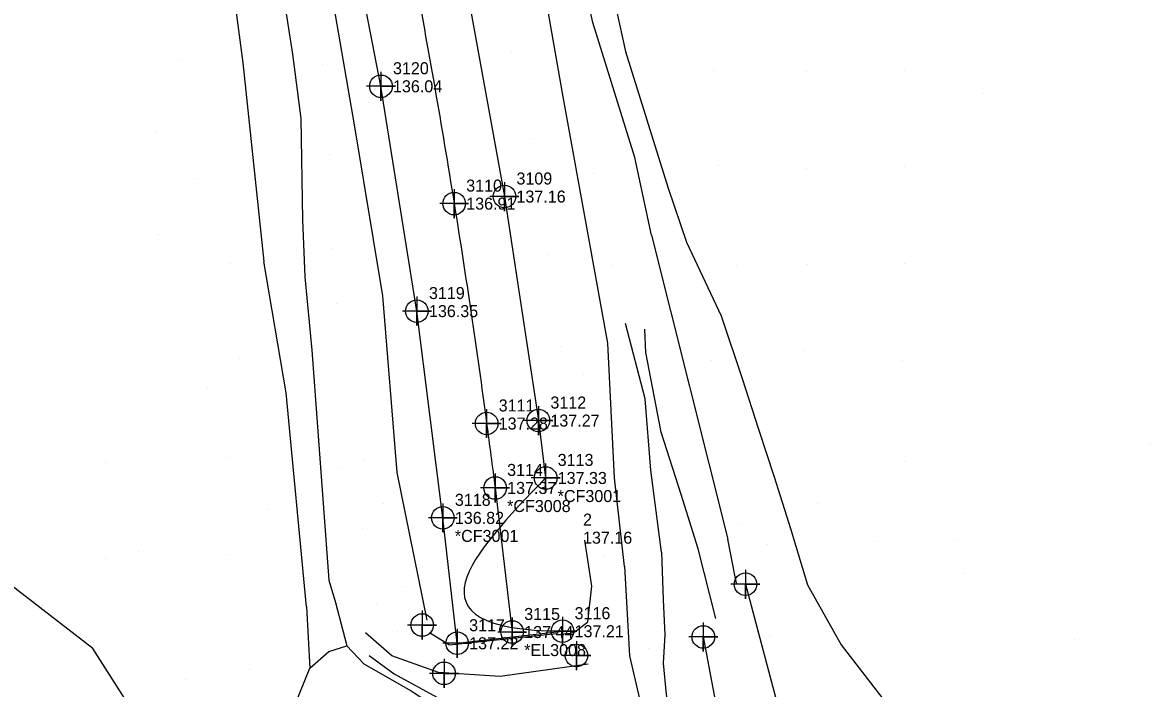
# Model space of a CAD drawing. Extents: x 2312183 to 2312663, y 819676 to 820746.
# Drawn here: x 2312371.9 to 2312606.3, y 820186.5 to 820324.9 of the extents above; entities that cross this region are included whole.
import ezdxf

# ---------------------------------------------------------------- set-up
doc = ezdxf.new("R2010")
doc.units = 0
for name, color, linetype in [('CTL Supplemental Horizontal and Vertical Cogo Elevation', 7, 'Continuous'), ('CTL Supplemental Horizontal and Vertical Cogo Number', 7, 'Continuous'), ('Exist DTM Breakline', 7, 'Continuous'), ('Exist DTM Breakline Cogo Point CELL', 7, 'Continuous'), ('Exist DTM Crownline', 7, 'Continuous'), ('Exist DTM Crownline Cogo Comment', 7, 'Continuous'), ('Exist DTM Crownline Cogo Elevation', 7, 'Continuous'), ('Exist DTM Crownline Cogo Number', 7, 'Continuous'), ('Exist DTM Crownline Cogo Point CELL', 7, 'Continuous'), ('Exist DTM Regular Point CELL', 7, 'Continuous'), ('Exist Roads EOP', 7, 'Continuous'), ('Exist Roads EOP Cogo Comment', 7, 'Continuous'), ('Exist Roads EOP Cogo Elevation', 7, 'Continuous'), ('Exist Roads EOP Cogo Number', 7, 'Continuous'), ('Exist Roads EOP Cogo Point CELL', 7, 'Continuous'), ('PH Exist DTM Breakline', 7, 'Continuous'), ('PH Exist DTM Point', 7, 'Continuous')]:
    doc.layers.add(name, color=color, linetype=linetype)

msp = doc.modelspace()

# ---------------------------------------------------------------- linework, layer by layer
at = {"layer": 'Exist DTM Breakline'}
for points in [[(2312522.0978, 820208.185), (2312528.7148, 820183.411), (2312536.4050000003, 820173.6053), (2312549.6083000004, 820163.9883)], [(2312513.3468, 820197.2374000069), (2312517.1413, 820177.0220999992)]]:
    msp.add_lwpolyline(points, dxfattribs=at)
at = {"layer": 'Exist DTM Breakline Cogo Point CELL'}
for points in [[(2312522.0978, 820211.1849999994), (2312522.0978, 820205.1849999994), (2312522.0978, 820208.1849999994), (2312525.0978, 820208.1849999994), (2312519.0978, 820208.1849999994)], [(2312513.3468, 820200.2374000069), (2312513.3468, 820194.2374000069), (2312513.3468, 820197.2374000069), (2312516.3468, 820197.2374000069), (2312510.3468, 820197.2374000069)]]:
    msp.add_lwpolyline(points, dxfattribs=at)
for centre in [(2312522.0978, 820208.1849999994), (2312513.3468, 820197.2374000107)]:
    msp.add_circle(centre, 2.344041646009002, dxfattribs=at)
at = {"layer": 'Exist DTM Crownline'}
msp.add_line((2312470.0837, 820228.1889), (2312473.6335, 820198.2664), dxfattribs=at)
msp.add_spline([(2312431.0822000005, 820427.0948), (2312442.7462, 820383.7602), (2312453.1289000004, 820335.5615000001), (2312461.5818, 820287.2566), (2312468.3305, 820241.5777), (2312470.0837, 820228.1889)], degree=3, dxfattribs=at)
at = {"layer": 'Exist DTM Crownline Cogo Point CELL'}
for points in [[(2312461.5818, 820290.2565999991), (2312461.5818, 820284.2565999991), (2312461.5818, 820287.2565999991), (2312464.5818, 820287.2565999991), (2312458.5818, 820287.2565999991)], [(2312461.5818, 820290.2565999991), (2312461.5818, 820284.2565999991), (2312461.5818, 820287.2565999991), (2312464.5818, 820287.2565999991), (2312458.5818, 820287.2565999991)], [(2312468.3305, 820244.5776999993), (2312468.3305, 820238.5776999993), (2312468.3305, 820241.5776999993), (2312471.3305, 820241.5776999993), (2312465.3305, 820241.5776999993)], [(2312468.3305, 820244.5776999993), (2312468.3305, 820238.5776999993), (2312468.3305, 820241.5776999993), (2312471.3305, 820241.5776999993), (2312465.3305, 820241.5776999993)], [(2312470.0837, 820231.1889000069), (2312470.0837, 820225.1889000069), (2312470.0837, 820228.1889000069), (2312473.0837, 820228.1889000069), (2312467.0837, 820228.1889000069)], [(2312470.0837, 820231.1889000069), (2312470.0837, 820225.1889000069), (2312470.0837, 820228.1889000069), (2312473.0837, 820228.1889000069), (2312467.0837, 820228.1889000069)], [(2312473.6335, 820201.266400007), (2312473.6335, 820195.266400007), (2312473.6335, 820198.266400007), (2312476.6335, 820198.266400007), (2312470.6335, 820198.266400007)], [(2312473.6335, 820201.266400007), (2312473.6335, 820195.266400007), (2312473.6335, 820198.266400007), (2312476.6335, 820198.266400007), (2312470.6335, 820198.266400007)]]:
    msp.add_lwpolyline(points, dxfattribs=at)
for centre in [(2312461.5818, 820287.2565999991), (2312461.5818, 820287.2565999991), (2312468.3305, 820241.5776999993), (2312468.3305, 820241.5776999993), (2312470.0837, 820228.1889000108), (2312470.0837, 820228.1889000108), (2312473.6335, 820198.2664000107), (2312473.6335, 820198.2664000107)]:
    msp.add_circle(centre, 2.344041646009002, dxfattribs=at)
at = {"layer": 'Exist DTM Regular Point CELL'}
for points in [[(2312454.915, 820202.7199999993), (2312454.915, 820196.7199999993), (2312454.915, 820199.7199999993), (2312457.915, 820199.7199999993), (2312451.915, 820199.7199999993)], [(2312486.9797, 820196.3685999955), (2312486.9797, 820190.3685999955), (2312486.9797, 820193.3685999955), (2312489.9797, 820193.3685999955), (2312483.9797, 820193.3685999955)], [(2312459.4753, 820192.6829000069), (2312459.4753, 820186.6829000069), (2312459.4753, 820189.6829000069), (2312462.4753, 820189.6829000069), (2312456.4753, 820189.6829000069)]]:
    msp.add_lwpolyline(points, dxfattribs=at)
for centre in [(2312454.915, 820199.7199999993), (2312486.9797, 820193.3685999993), (2312459.4753, 820189.6829000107)]:
    msp.add_circle(centre, 2.344041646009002, dxfattribs=at)
at = {"layer": 'Exist Roads EOP'}
msp.add_line((2312462.1894999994, 820195.9283000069), (2312459.2241, 820221.9777), dxfattribs=at)
for points in [[(2312441.0535, 820429.753), (2312452.7654, 820386.6268), (2312463.4794, 820336.0054), (2312472.0187, 820288.7267000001), (2312479.0736, 820242.1885), (2312480.5877, 820230.2653)], [(2312459.2241, 820221.9777), (2312453.8417, 820264.9341), (2312446.3695, 820311.6319000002), (2312437.1934, 820358.8933), (2312425.9943, 820405.6538), (2312419.7593, 820426.9969)], [(2312462.1895, 820195.928300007), (2312484.0977, 820198.4309999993)]]:
    msp.add_lwpolyline(points, dxfattribs=at)
msp.add_spline([(2312480.5877, 820230.2653), (2312484.0977, 820198.431), (2312484.0977, 820198.4309999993)], degree=3, dxfattribs=at)
at = {"layer": 'Exist Roads EOP Cogo Point CELL'}
for points in [[(2312446.3695, 820314.6318999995), (2312446.3695, 820308.6318999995), (2312446.3695, 820311.6318999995), (2312449.3695, 820311.6318999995), (2312443.3695, 820311.6318999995)], [(2312446.3695, 820314.6318999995), (2312446.3695, 820308.6318999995), (2312446.3695, 820311.6318999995), (2312449.3695, 820311.6318999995), (2312443.3695, 820311.6318999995)], [(2312446.3695, 820314.6318999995), (2312446.3695, 820308.6318999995), (2312446.3695, 820311.6318999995), (2312449.3695, 820311.6318999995), (2312443.3695, 820311.6318999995)], [(2312472.0187, 820291.7266999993), (2312472.0187, 820285.7266999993), (2312472.0187, 820288.7266999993), (2312475.0187, 820288.7266999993), (2312469.0187, 820288.7266999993)], [(2312472.0187, 820291.7266999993), (2312472.0187, 820285.7266999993), (2312472.0187, 820288.7266999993), (2312475.0187, 820288.7266999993), (2312469.0187, 820288.7266999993)], [(2312472.0187, 820291.7266999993), (2312472.0187, 820285.7266999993), (2312472.0187, 820288.7266999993), (2312475.0187, 820288.7266999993), (2312469.0187, 820288.7266999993)], [(2312453.8417, 820267.9340999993), (2312453.8417, 820261.9340999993), (2312453.8417, 820264.9340999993), (2312456.8417, 820264.9340999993), (2312450.8417, 820264.9340999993)], [(2312453.8417, 820267.9340999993), (2312453.8417, 820261.9340999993), (2312453.8417, 820264.9340999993), (2312456.8417, 820264.9340999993), (2312450.8417, 820264.9340999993)], [(2312453.8417, 820267.9340999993), (2312453.8417, 820261.9340999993), (2312453.8417, 820264.9340999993), (2312456.8417, 820264.9340999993), (2312450.8417, 820264.9340999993)], [(2312479.0736, 820245.1884999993), (2312479.0736, 820239.1884999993), (2312479.0736, 820242.1884999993), (2312482.0736, 820242.1884999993), (2312476.0736, 820242.1884999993)], [(2312479.0736, 820245.1884999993), (2312479.0736, 820239.1884999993), (2312479.0736, 820242.1884999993), (2312482.0736, 820242.1884999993), (2312476.0736, 820242.1884999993)], [(2312479.0736, 820245.1884999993), (2312479.0736, 820239.1884999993), (2312479.0736, 820242.1884999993), (2312482.0736, 820242.1884999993), (2312476.0736, 820242.1884999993)], [(2312480.5877, 820233.2652999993), (2312480.5877, 820227.2652999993), (2312480.5877, 820230.2652999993), (2312483.5877, 820230.2652999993), (2312477.5877, 820230.2652999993)], [(2312480.5877, 820233.2652999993), (2312480.5877, 820227.2652999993), (2312480.5877, 820230.2652999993), (2312483.5877, 820230.2652999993), (2312477.5877, 820230.2652999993)], [(2312480.5877, 820233.2652999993), (2312480.5877, 820227.2652999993), (2312480.5877, 820230.2652999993), (2312483.5877, 820230.2652999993), (2312477.5877, 820230.2652999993)], [(2312459.2241, 820224.9776999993), (2312459.2241, 820218.9776999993), (2312459.2241, 820221.9776999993), (2312462.2241, 820221.9776999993), (2312456.2241, 820221.9776999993)], [(2312459.2241, 820224.9776999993), (2312459.2241, 820218.9776999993), (2312459.2241, 820221.9776999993), (2312462.2241, 820221.9776999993), (2312456.2241, 820221.9776999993)], [(2312459.2241, 820224.9776999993), (2312459.2241, 820218.9776999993), (2312459.2241, 820221.9776999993), (2312462.2241, 820221.9776999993), (2312456.2241, 820221.9776999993)], [(2312484.0977, 820201.4309999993), (2312484.0977, 820195.4309999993), (2312484.0977, 820198.4309999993), (2312487.0977, 820198.4309999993), (2312481.0977, 820198.4309999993)], [(2312484.0977, 820201.4309999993), (2312484.0977, 820195.4309999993), (2312484.0977, 820198.4309999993), (2312487.0977, 820198.4309999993), (2312481.0977, 820198.4309999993)], [(2312484.0977, 820201.4309999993), (2312484.0977, 820195.4309999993), (2312484.0977, 820198.4309999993), (2312487.0977, 820198.4309999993), (2312481.0977, 820198.4309999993)], [(2312462.1895, 820198.928300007), (2312462.1895, 820192.928300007), (2312462.1895, 820195.928300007), (2312465.1895, 820195.928300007), (2312459.1895, 820195.928300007)], [(2312462.1895, 820198.928300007), (2312462.1895, 820192.928300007), (2312462.1895, 820195.928300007), (2312465.1895, 820195.928300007), (2312459.1895, 820195.928300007)], [(2312462.1895, 820198.928300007), (2312462.1895, 820192.928300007), (2312462.1895, 820195.928300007), (2312465.1895, 820195.928300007), (2312459.1895, 820195.928300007)]]:
    msp.add_lwpolyline(points, dxfattribs=at)
for centre in [(2312446.3695, 820311.6318999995), (2312446.3695, 820311.6318999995), (2312446.3695, 820311.6318999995), (2312472.0187, 820288.7266999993), (2312472.0187, 820288.7266999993), (2312472.0187, 820288.7266999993), (2312453.8417, 820264.9340999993), (2312453.8417, 820264.9340999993), (2312453.8417, 820264.9340999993), (2312479.0736, 820242.1884999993), (2312479.0736, 820242.1884999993), (2312479.0736, 820242.1884999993), (2312480.5877, 820230.2652999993), (2312480.5877, 820230.2652999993), (2312480.5877, 820230.2652999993), (2312459.2241, 820221.9776999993), (2312459.2241, 820221.9776999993), (2312459.2241, 820221.9776999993), (2312484.0977, 820198.4309999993), (2312484.0977, 820198.4309999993), (2312484.0977, 820198.4309999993), (2312462.1895, 820195.9283000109), (2312462.1895, 820195.9283000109), (2312462.1895, 820195.9283000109)]:
    msp.add_circle(centre, 2.344041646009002, dxfattribs=at)
at = {"layer": 'PH Exist DTM Breakline'}
for points in [[(2312496.9827015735, 820211.8866744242), (2312494.8731904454, 820230.3124907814), (2312493.519987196, 820258.2712960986), (2312489.5697944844, 820280.073130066), (2312484.2208748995, 820309.4534036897), (2312481.150772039, 820326.8098322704), (2312475.4411637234, 820352.0844131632), (2312471.9095048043, 820367.9236878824), (2312467.912111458, 820381.4585456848), (2312463.4561038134, 820397.0129259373), (2312457.4207705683, 820416.5983887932), (2312453.9249898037, 820433.7888603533), (2312449.599353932, 820447.3666451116), (2312444.372751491, 820464.2727058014), (2312438.966790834, 820481.2008368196), (2312434.255033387, 820489.9728212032), (2312425.0514561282, 820503.8371172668), (2312418.259878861, 820512.3555225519), (2312411.0550560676, 820524.7736185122), (2312404.5014063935, 820537.3120355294), (2312396.0707229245, 820550.9142930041), (2312386.9718457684, 820563.2584496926), (2312378.040674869, 820577.4175645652), (2312367.5173050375, 820592.3718469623)], [(2312323.1852827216, 820565.0943421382), (2312341.16408717, 820534.9037687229), (2312360.245174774, 820506.1026928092), (2312372.4134060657, 820480.8900151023), (2312378.9962576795, 820463.915286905), (2312383.7723335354, 820454.9488229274), (2312388.746726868, 820444.6210026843), (2312396.2505561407, 820429.0479748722), (2312399.85680621, 820410.3493696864), (2312407.6810818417, 820378.7675660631), (2312412.990038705, 820355.2448037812), (2312416.1657901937, 820328.0193103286), (2312417.670236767, 820316.518029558), (2312422.048230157, 820275.2675484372)], [(2312457.310195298, 820470.8861366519), (2312462.7773111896, 820457.1940474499), (2312468.029919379, 820441.2262342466), (2312476.135823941, 820415.8221279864), (2312481.1635680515, 820399.2820110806), (2312486.56663762, 820374.1366036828), (2312491.175310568, 820346.3471255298), (2312497.1618455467, 820318.8853012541), (2312506.0476551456, 820290.4807863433), (2312509.857743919, 820279.2465673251), (2312517.034249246, 820263.9694193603), (2312521.4019957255, 820250.9366621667), (2312524.806534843, 820240.42459485), (2312528.0448119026, 820230.484835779), (2312531.475516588, 820219.8051016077)], [(2312391.1625844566, 820470.3831024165), (2312395.47620005, 820461.7769371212), (2312400.382861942, 820454.8597855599), (2312403.1375107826, 820447.0263515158), (2312404.5621205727, 820436.917011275), (2312406.087167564, 820429.8943630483), (2312407.398139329, 820424.4934151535), (2312408.6872812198, 820418.1584440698), (2312410.6680697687, 820411.7899121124), (2312412.8573282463, 820405.2837896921), (2312415.74816436, 820396.579647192), (2312418.226217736, 820388.7645800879), (2312419.520083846, 820381.7036929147), (2312419.4184755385, 820374.2083282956), (2312421.1745975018, 820356.993459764), (2312423.458423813, 820344.7491194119), (2312425.7778383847, 820332.5817705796), (2312428.009826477, 820318.2808153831), (2312429.6954572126, 820304.9376266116), (2312430.078320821, 820283.9125766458), (2312430.5516890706, 820272.0198299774), (2312432.00627728, 820256.8034783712), (2312435.527714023, 820209.0178143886), (2312436.9438508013, 820204.4279931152)], [(2312455.9897626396, 820200.7254818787), (2312449.7528222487, 820231.3712196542), (2312446.7479994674, 820268.1101860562), (2312440.8961120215, 820303.6189076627), (2312436.924257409, 820326.4967031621), (2312429.9949859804, 820358.7432979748), (2312425.222767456, 820386.427209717), (2312419.514405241, 820406.4620079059)], [(2312502.6086706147, 820280.6943650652), (2312499.1044130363, 820296.8141767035), (2312490.4258541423, 820324.8778059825), (2312485.2126725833, 820348.1042641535), (2312480.716840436, 820367.4848794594), (2312479.8130631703, 820378.4907109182), (2312477.1584266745, 820390.3024518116)], [(2312502.6086706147, 820280.6943650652), (2312518.4378753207, 820217.5422396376)], [(2312430.8656834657, 820203.4897764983), (2312426.6712827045, 820247.9673115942), (2312422.048230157, 820275.2675484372)], [(2312504.654031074, 820214.8544357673), (2312502.4163337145, 820231.8909139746), (2312501.265166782, 820246.7144320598), (2312497.166275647, 820262.3420951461)], [(2312512.3112645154, 820215.577665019), (2312508.7192807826, 820226.8312340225), (2312504.588204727, 820239.7737618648), (2312501.421432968, 820256.3451421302), (2312501.1618723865, 820261.1587671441)], [(2312393.105147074, 820184.5247498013), (2312386.5189976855, 820194.8381155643), (2312368.796839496, 820208.5331883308), (2312355.1234224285, 820217.698035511), (2312339.6182844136, 820221.5806210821), (2312322.8810238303, 820219.6650170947)], [(2312531.475516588, 820219.8051016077), (2312535.0077930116, 820208.0406104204), (2312541.9563559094, 820195.6180088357), (2312554.8747570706, 820178.9291354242), (2312565.8373415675, 820168.7782051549)], [(2312483.076744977, 820197.7595365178), (2312485.7928966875, 820198.0427657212), (2312486.62397548, 820198.2889687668), (2312489.3686033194, 820200.3805491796), (2312490.1541969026, 820207.7897443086), (2312488.7099424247, 820217.3608684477)], [(2312520.323941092, 820208.1553569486), (2312519.970935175, 820209.7020465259), (2312518.4378753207, 820217.5422396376)], [(2312515.923391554, 820201.0869982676), (2312512.3112645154, 820215.577665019)], [(2312504.654031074, 820214.8544357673), (2312504.971742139, 820204.9672724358), (2312505.3259056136, 820197.706687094), (2312504.9721468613, 820191.7820194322), (2312505.6152762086, 820185.2689411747), (2312507.1140928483, 820177.4336875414), (2312507.9955755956, 820173.0052529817), (2312508.7725000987, 820169.7525202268), (2312509.5947601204, 820167.0419744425)], [(2312496.9827015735, 820211.8866744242), (2312497.5801130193, 820200.803214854), (2312498.0139435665, 820193.2870985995), (2312500.7975053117, 820181.41640712), (2312503.905670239, 820170.3597104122), (2312505.6439292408, 820164.9681985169)], [(2312430.8656834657, 820203.4897764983), (2312431.6216839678, 820190.7706476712)], [(2312436.9438508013, 820204.4279931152), (2312439.284360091, 820195.4310662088)], [(2312489.429089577, 820191.617272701), (2312471.10760166, 820189.0069712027), (2312458.3514873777, 820189.8379575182), (2312448.63398591, 820193.2901517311), (2312443.16448791, 820198.0738813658)], [(2312482.7691981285, 820197.9087819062), (2312460.5941557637, 820195.5590013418), (2312456.47517117, 820198.1011321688)], [(2312428.088481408, 820143.2586481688), (2312429.579291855, 820147.5779860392), (2312430.952714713, 820174.1035224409), (2312428.4963619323, 820183.0640395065), (2312431.6216839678, 820190.7706476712), (2312435.5434535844, 820194.2249732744), (2312439.284360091, 820195.4310662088), (2312442.8297548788, 820191.6670792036), (2312452.6290186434, 820186.0786191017), (2312462.3400134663, 820179.5938346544)], [(2312443.923482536, 820193.4184290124), (2312449.1447323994, 820189.5901366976), (2312458.7106638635, 820184.289904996), (2312471.764806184, 820180.4186868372), (2312480.7080911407, 820178.2551435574), (2312488.1254134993, 820176.635094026), (2312494.8126173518, 820169.9121056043), (2312498.3363931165, 820165.1740643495)]]:
    msp.add_lwpolyline(points, dxfattribs=at)
at = {"layer": 'PH Exist DTM Point'}
for p, q in [((2312473.497548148, 820318.6508580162), (2312473.497548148, 820318.6508580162)), ((2312404.873871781, 820317.2982642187), (2312404.873871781, 820317.2982642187)), ((2312434.2709308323, 820316.2020480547), (2312434.2709308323, 820316.2020480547)), ((2312515.4610106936, 820314.8754762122), (2312515.4610106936, 820314.8754762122)), ((2312534.780202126, 820314.6581715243), (2312534.780202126, 820314.6581715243)), ((2312555.2075333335, 820314.8277703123), (2312555.2075333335, 820314.8277703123)), ((2312571.495976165, 820310.1774057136), (2312571.495976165, 820310.1774057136)), ((2312399.4243623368, 820302.2160696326), (2312399.4243623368, 820302.2160696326)), ((2312477.338344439, 820300.8742648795), (2312477.338344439, 820300.8742648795)), ((2312435.728662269, 820297.5494028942), (2312435.728662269, 820297.5494028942)), ((2312516.4410757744, 820295.1882994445), (2312516.4410757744, 820295.1882994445)), ((2312555.20064002, 820294.8753709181), (2312555.20064002, 820294.8753709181)), ((2312408.263891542, 820292.5782552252), (2312408.263891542, 820292.5782552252)), ((2312490.498565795, 820293.6092863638), (2312490.498565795, 820293.6092863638)), ((2312534.801376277, 820294.5660066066), (2312534.801376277, 820294.5660066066)), ((2312400.2266808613, 820280.8348231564), (2312400.2266808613, 820280.8348231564)), ((2312436.3368793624, 820277.9166533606), (2312436.3368793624, 820277.9166533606)), ((2312481.083632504, 820276.6701394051), (2312481.083632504, 820276.6701394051)), ((2312415.176717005, 820274.7847335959), (2312415.176717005, 820274.7847335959)), ((2312494.3629959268, 820274.4672997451), (2312494.3629959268, 820274.4672997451)), ((2312520.171978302, 820274.4501454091), (2312520.171978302, 820274.4501454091)), ((2312534.9073861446, 820274.6987669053), (2312534.9073861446, 820274.6987669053)), ((2312555.202085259, 820274.792830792), (2312555.202085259, 820274.792830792)), ((2312437.165122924, 820266.5565329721), (2312437.165122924, 820266.5565329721)), ((2312483.6143754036, 820257.4944048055), (2312483.6143754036, 820257.4944048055)), ((2312416.925901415, 820255.0522742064), (2312416.925901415, 820255.0522742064)), ((2312534.3080178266, 820256.8397969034), (2312534.3080178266, 820256.8397969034)), ((2312515.111772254, 820254.7557605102), (2312515.111772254, 820254.7557605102)), ((2312554.8103842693, 820254.6678052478), (2312554.8103842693, 820254.6678052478)), ((2312488.5143102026, 820251.7678746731), (2312488.5143102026, 820251.7678746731)), ((2312410.2829301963, 820248.969042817), (2312410.2829301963, 820248.969042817)), ((2312606.2535485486, 820237.4582140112), (2312606.2535485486, 820237.4582140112)), ((2312414.8311172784, 820234.4728290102), (2312414.8311172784, 820234.4728290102)), ((2312442.637377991, 820234.1901274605), (2312442.637377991, 820234.1901274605)), ((2312389.1426887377, 820233.5023981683), (2312389.1426887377, 820233.5023981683)), ((2312438.0803147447, 820232.4482524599), (2312438.0803147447, 820232.4482524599)), ((2312555.08878179, 820233.6655744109), (2312555.08878179, 820233.6655744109)), ((2312446.895194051, 820224.9859256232), (2312446.895194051, 820224.9859256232)), ((2312537.005316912, 820225.03471983), (2312537.005316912, 820225.03471983)), ((2312423.084125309, 820223.7794715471), (2312423.084125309, 820223.7794715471)), ((2312442.6160341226, 820219.8456502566), (2312442.6160341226, 820219.8456502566)), ((2312521.295424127, 820220.5667598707), (2312521.295424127, 820220.5667598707)), ((2312566.0653547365, 820217.5070337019), (2312566.0653547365, 820217.5070337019)), ((2312526.652472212, 820216.4076721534), (2312526.652472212, 820216.4076721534)), ((2312548.855673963, 820217.0626046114), (2312548.855673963, 820217.0626046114)), ((2312389.1426887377, 820213.5023981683), (2312389.1426887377, 820213.5023981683)), ((2312396.074837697, 820214.9574895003), (2312396.074837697, 820214.9574895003)), ((2312414.841971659, 820214.4388225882), (2312414.841971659, 820214.4388225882)), ((2312492.9118470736, 820214.0518799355), (2312492.9118470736, 820214.0518799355)), ((2312567.6859302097, 820210.3613491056), (2312567.6859302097, 820210.3613491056)), ((2312450.814799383, 820207.6339279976), (2312450.814799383, 820207.6339279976)), ((2312445.4514637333, 820204.2772146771), (2312445.4514637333, 820204.2772146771)), ((2312449.8616656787, 820198.3149098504), (2312449.8616656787, 820198.3149098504)), ((2312527.055238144, 820197.544230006), (2312527.055238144, 820197.544230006)), ((2312590.472644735, 820196.6915455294), (2312590.472644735, 820196.6915455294)), ((2312501.9924818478, 820194.8060683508), (2312501.9924818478, 820194.8060683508)), ((2312419.121184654, 820190.5482577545), (2312419.121184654, 820190.5482577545)), ((2312405.807020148, 820188.4225819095), (2312405.807020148, 820188.4225819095))]:
    msp.add_line(p, q, dxfattribs=at)

# ---------------------------------------------------------------- texts
at = {"layer": 'CTL Supplemental Horizontal and Vertical Cogo Elevation'}
msp.add_text('137.16', height=2.5, dxfattribs=at).set_placement((2312488.352, 820216.6140000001))
at = {"layer": 'CTL Supplemental Horizontal and Vertical Cogo Number'}
msp.add_text('2', height=2.5, dxfattribs=at).set_placement((2312488.352, 820220.3640000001))
at = {"layer": 'Exist DTM Crownline Cogo Comment'}
for s, p in [('*CF3008', (2312472.5837, 820223.1889)), ('*EL3008', (2312476.1335, 820193.2664))]:
    msp.add_text(s, height=2.5, dxfattribs=at).set_placement(p)
at = {"layer": 'Exist DTM Crownline Cogo Elevation'}
for s, p in [('136.91', (2312464.0818, 820286.0066)), ('137.28', (2312470.8305, 820240.3277)), ('137.37', (2312472.5837, 820226.9389)), ('137.44', (2312476.1335, 820197.0164))]:
    msp.add_text(s, height=2.5, dxfattribs=at).set_placement(p)
at = {"layer": 'Exist DTM Crownline Cogo Number'}
for s, p in [('3110', (2312464.0818, 820289.7566)), ('3111', (2312470.8305, 820244.0777)), ('3114', (2312472.5837, 820230.6889)), ('3115', (2312476.1335, 820200.7664))]:
    msp.add_text(s, height=2.5, dxfattribs=at).set_placement(p)
at = {"layer": 'Exist Roads EOP Cogo Comment'}
for p in [(2312483.0877, 820225.2653), (2312461.7241, 820216.9777)]:
    msp.add_text('*CF3001', height=2.5, dxfattribs=at).set_placement(p)
at = {"layer": 'Exist Roads EOP Cogo Elevation'}
for s, p in [('136.04', (2312448.8695, 820310.3819000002)), ('137.16', (2312474.5187, 820287.4767000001)), ('136.35', (2312456.3417, 820263.6841)), ('137.27', (2312481.5736, 820240.9385)), ('137.33', (2312483.0877, 820229.0153)), ('136.82', (2312461.7241, 820220.7277)), ('137.21', (2312486.5977, 820197.181)), ('137.22', (2312464.6895, 820194.6783000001))]:
    msp.add_text(s, height=2.5, dxfattribs=at).set_placement(p)
at = {"layer": 'Exist Roads EOP Cogo Number'}
for s, p in [('3120', (2312448.8695, 820314.1319000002)), ('3109', (2312474.5187, 820291.2267000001)), ('3119', (2312456.3417, 820267.4341)), ('3112', (2312481.5736, 820244.6885)), ('3113', (2312483.0877, 820232.7653)), ('3118', (2312461.7241, 820224.4777)), ('3116', (2312486.5977, 820200.931)), ('3117', (2312464.6895, 820198.4283000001))]:
    msp.add_text(s, height=2.5, dxfattribs=at).set_placement(p)

doc.saveas('drawing.dxf')
